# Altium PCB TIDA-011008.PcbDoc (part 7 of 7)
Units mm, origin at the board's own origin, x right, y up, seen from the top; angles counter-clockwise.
Board outline 252 x 205 mm, 4 copper layers (Top Layer, Inner Layer 1, Inner Layer 2, Bottom Layer), stack 1.926 mm thick; 517 components, 293 nets, 1426 pads, 1855 vias.
Unrouted connection lines stored in the file: 4.
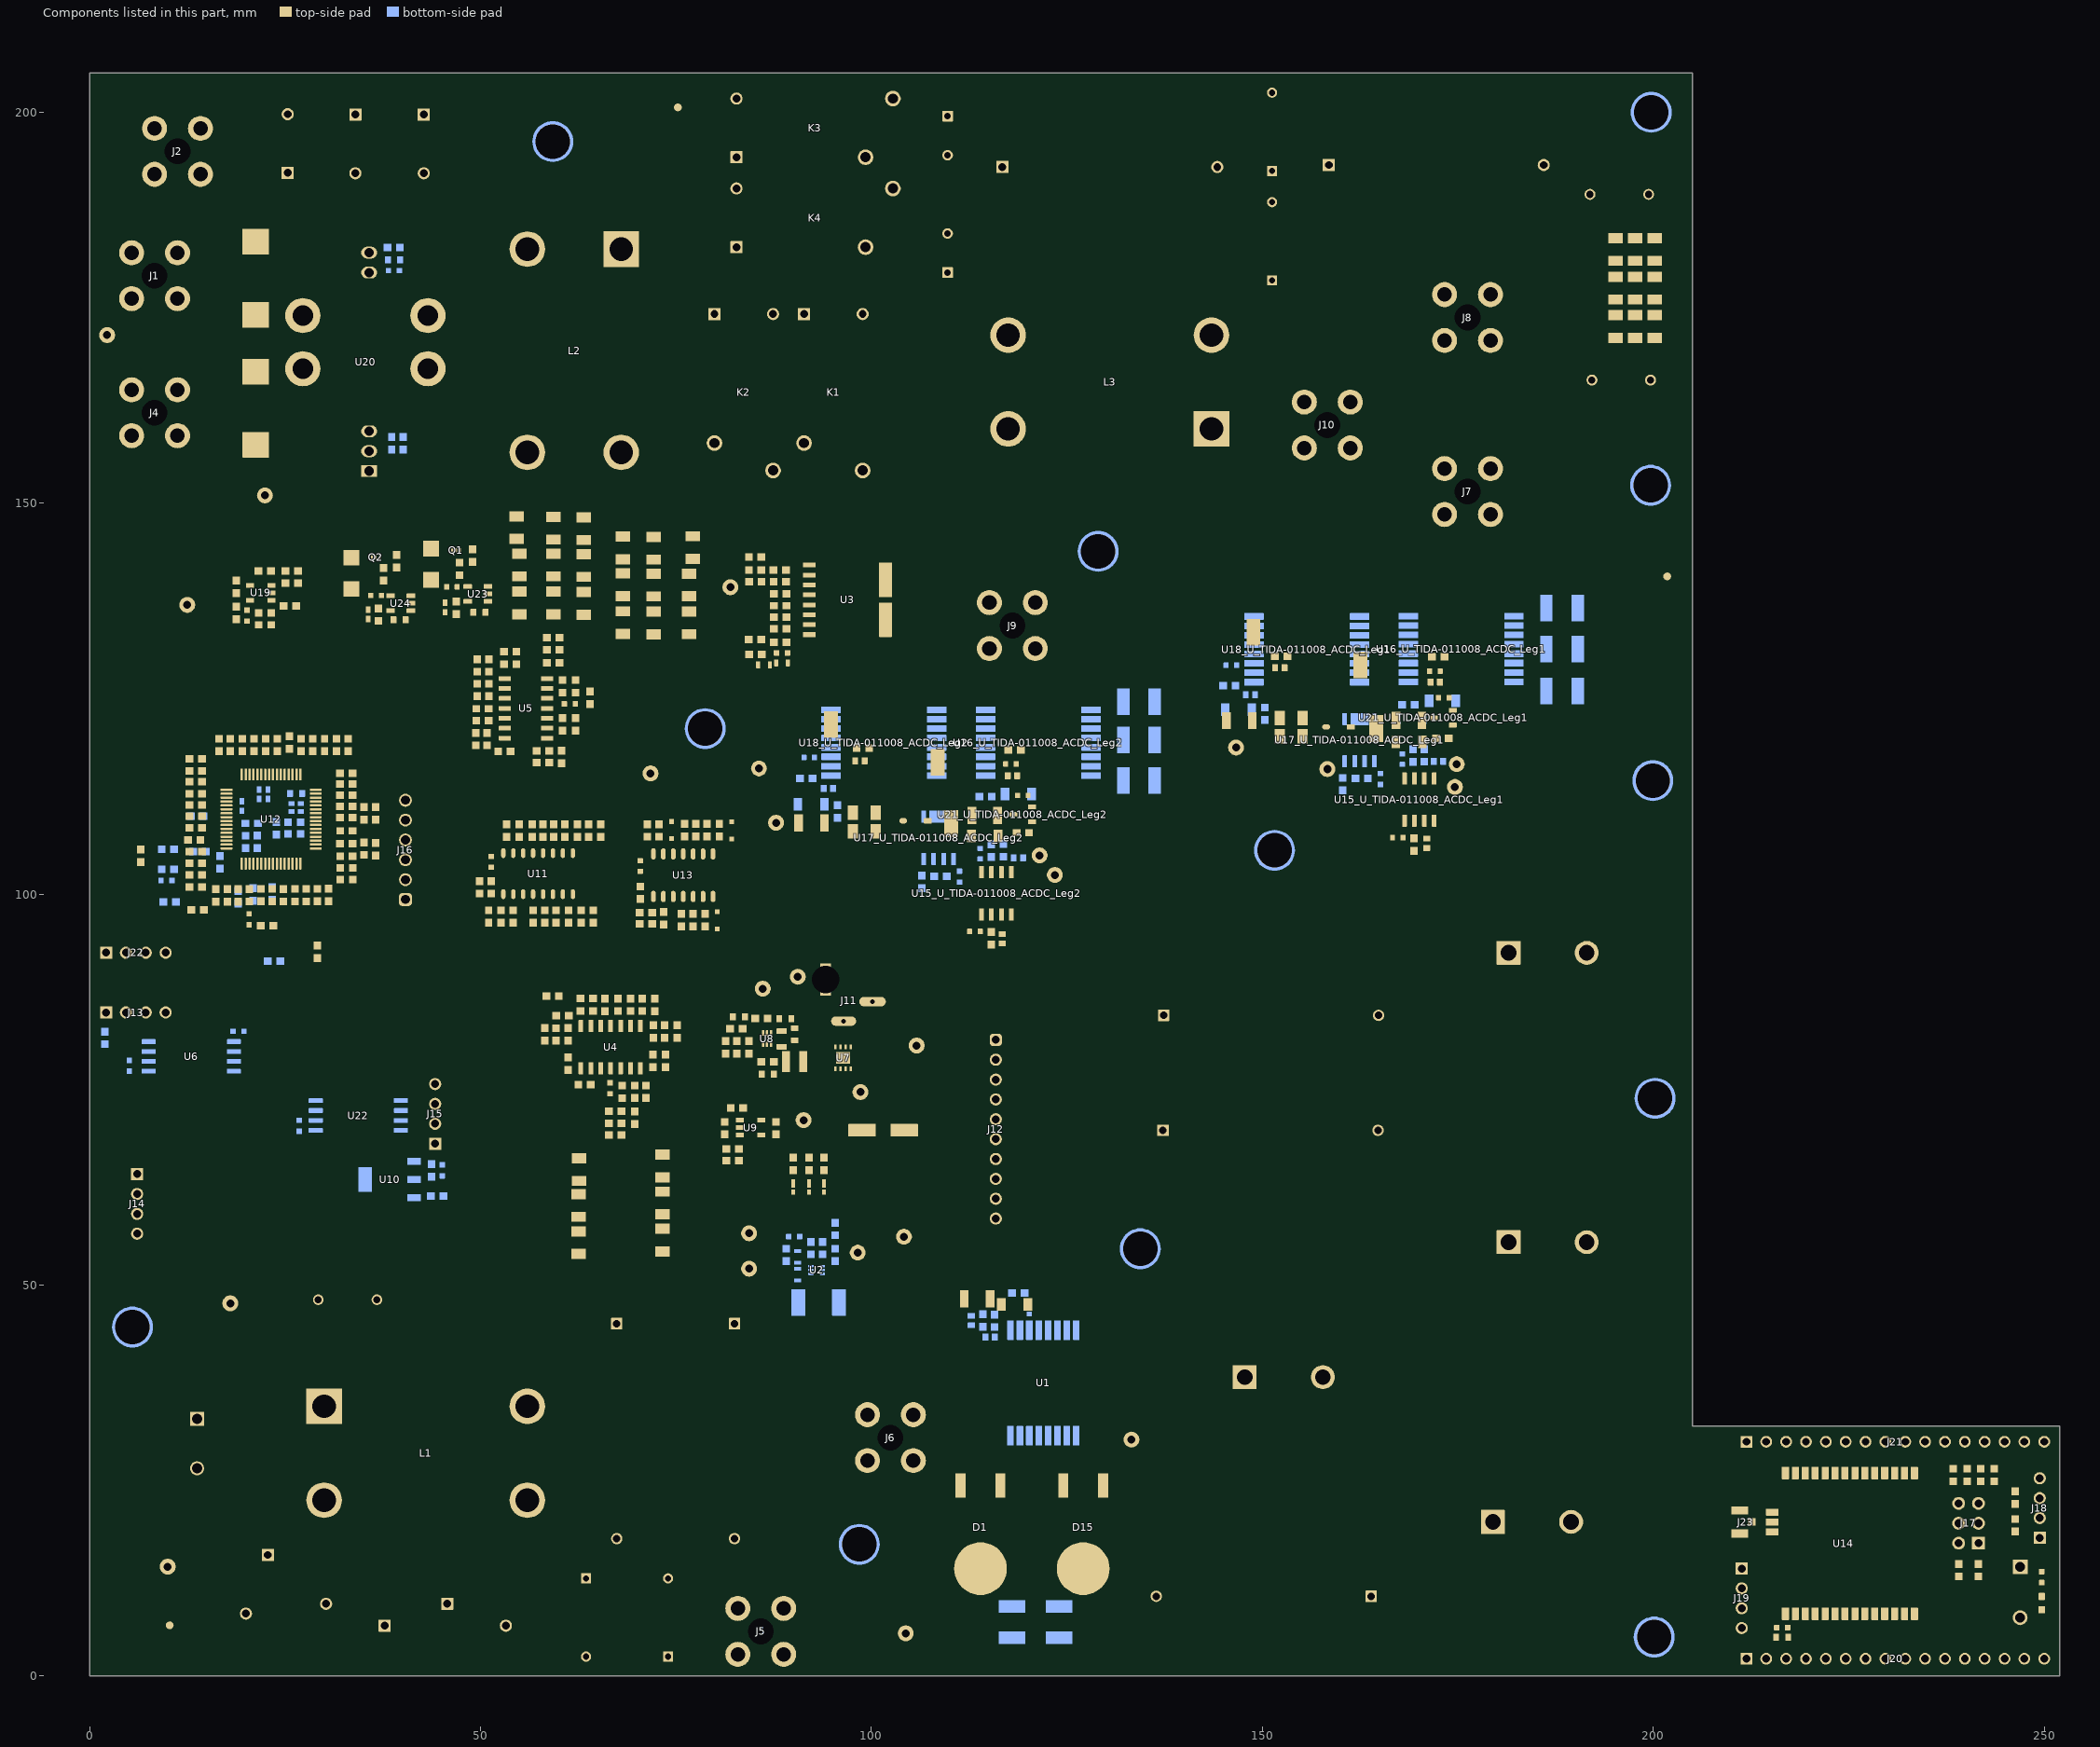
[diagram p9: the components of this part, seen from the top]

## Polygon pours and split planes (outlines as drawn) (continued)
DC_Bus- on Bottom Layer "BOTTOM_LAYER_DC_BUS-_P165" (solid, pour order 165): 143.567,131.562 139.741,127.736 136.518,127.736 135.5,128.754 135.5,139.871 140.784,145.155 143.567,142.372
VCC_3V3 on Bottom Layer "BOTTOM_LAYER_VCC_3V3_P149" (solid, pour order 149): 21.04,109.531 21.062,109.552 22.065,109.552 22.065,109.477 23.377,108.165 25.865,108.165 25.865,107.115 25.779,107.029 20.99,107.029 20.99,107.252
DC_Bus+ on Bottom Layer "BOTTOM_LAYER_DC_BUS+_P134" (solid, pour order 134): 125.15,129.32 130.36,134.53 132.475,134.53 133.061,133.944 133.061,104.966 132.596,104.501 129.823,104.501 125.15,109.174
DC_Bus- on Bottom Layer "BOTTOM_LAYER_DC_BUS-_P139" (solid, pour order 139): 189.51,140.915 190.871,142.277 197.293,142.277 203,136.569 203,118.589 200.908,116.496 190.215,116.496 189.51,117.202
DC_Bus- on Bottom Layer "BOTTOM_LAYER_DC_BUS-_P138" (solid, pour order 138): 135.519,128.873 136.074,129.429 138.071,129.429 139.75,127.75 139.75,108.665 137.235,106.15 136,106.15 135.5,106.65 135.5,128.864 135.519,128.882
DC_Bus- on Bottom Layer "BOTTOM_LAYER_DC_BUS-_P136" (solid, pour order 136): 153.242,131.562 153.904,132.224 153.904,144.337 153.086,145.155 140.784,145.155 135.76,140.131 135.76,133.842 138.04,131.562
DC_Bus- on Bottom Layer "BOTTOM_LAYER_DC_BUS-_P135" (solid, pour order 135): 102.67,119.566 103.271,120.168 103.271,127.176 102.697,127.75 93.153,127.75 91.378,125.974 91.378,120.742 92.553,119.567 92.553,119.566
AC_N on Bottom Layer "BOTTOM_LAYER_AC_N_P097" (solid, pour order 97): 4.715,167.2 15.05,167.2 23.75,158.5 23.75,154.94 22.31,153.5 5.42,153.5 2.719,156.201 2.719,165.203
NetF1_1 on Bottom Layer "BOTTOM_LAYER_NETF1_1_P089" (solid, pour order 89): 19.25,177 29,177 30,176 30,172.739 28.669,171.408 19.842,171.408 18.75,172.5 18.75,176.5
NetL2_3 on Bottom Layer "BOTTOM_LAYER_NETL2_3_P085" (solid, pour order 85): 43.687,179 50.75,179 62.5,167.25 62.5,154.339 60.411,152.25 52.75,152.25 50.5,154.5 50.5,165.75 44.511,171.739 41.908,171.739 41.125,172.522 41.125,176.438
VAC_N_SW on Bottom Layer "BOTTOM_LAYER_VAC_N_SW_P074" (solid, pour order 74): 118.25,204.25 153.25,204.25 154.25,203.25 154.25,200.5 153.25,199.5 125.375,199.5 124.25,198.375
VAC_N_SW on Bottom Layer "BOTTOM_LAYER_VAC_N_SW_P061" (solid, pour order 61): 19 vertices, not listed, extent 99.25,153.727 131.5,204.25
NetC26_1 on Bottom Layer "BOTTOM_LAYER_NETC26_1_P052" (solid, pour order 52): 140.75,163 149.565,163 152.565,166 165.987,166 168.25,163.737 168.25,158 164.5,154.25 141.25,154.25 140,155.5 140,162.25
NetC25_2 on Bottom Layer "BOTTOM_LAYER_NETC25_2_P050" (solid, pour order 50): 156.187,174.5 160.437,178.75 182.25,178.75 183.5,177.5 183.5,169.25 181.828,167.578 168.672,167.578 141.422,167.578 138.75,170.25 138.75,173.5 139.75,174.5
SN1 on Bottom Layer "BOTTOM_LAYER_SN1_P046" (solid, pour order 46): 160.298,121.504 164.589,121.504 165.104,122.018 165.104,130.139 166.527,131.562 170.124,131.562 173.212,134.65 173.212,139.962 181.039,147.789 181.039,155.224 179.979,156.284 171.363,156.284 157.75,142.671 157.75,124.052
PV_Input+ on Bottom Layer "BOTTOM_LAYER_PV_INPUT+_P019" (solid, pour order 19): 9,28.5 26,28.5 28.25,26.25 35.75,26.25 36.5,25.5 36.5,17 36.25,16.75 27.25,16.75 23.5,20.5 9.25,20.5 9,20.75
PV_Input+ on Bottom Layer "BOTTOM_LAYER_PV_INPUT+_P016" (solid, pour order 16): 11.5,20.75 15.25,17 15.25,8.5 18.25,5.5 30.8,5.5 32.241,6.941 32.241,10.121 31.162,11.2 21.3,11.2 18.25,14.25 18.25,20 19,20.75
PV_Input- on Bottom Layer "BOTTOM_LAYER_PV_INPUT-_P005" (solid, pour order 5): 9,30.25 26.25,30.25 28.5,28 35.5,28 36.5,29 36.5,38.5 35,40 9,40
DC_Bus- on Inner Layer 2 "INNER_LAYER_2_DC_BUS-_P255" (solid, remove dead copper, pour order 255): 77 vertices, not listed, extent 1,41.201 174.046,146.75
NetL2_3 on Inner Layer 2 "Inner Layer 2-NetL2_3" (solid, pour order 269): 40.959,173.023 42.574,171.408 47.694,171.408 49.5,173.214 49.5,184.679 40.774,193.405 23.75,193.405 23.75,189.588 25.838,187.5 39.638,187.5 43.687,183.45 43.687,179 40.959,176.271
DC_Bus- on Inner Layer 2 "Inner Layer 2-DC_Bus-" (solid, pour order 263): 67 vertices, not listed, extent 91.378,0.647 203,144.337
NetC8_2 on Inner Layer 2 "INNER_LAYER_2_NETC8_2_P240" (solid, pour order 240): 18 vertices, not listed, extent 53.125,0.25 91.553,25.261
NetL2_4 on Inner Layer 2 "INNER_LAYER_2_NETL2_4_P234" (solid, pour order 234): 40.56,167.885 42.175,169.5 47.083,169.5 48.25,168.333 48.25,165.5 46.25,163.5 42.496,163.5 40.56,165.435
GND_WiFi on Inner Layer 2 "INNER_LAYER_2_GND_WIFI_P229" (solid, pour order 229): 34.493,65.814 16.698,65.814 9.73,72.781 9.73,77.357 1.738,77.357 1,78.095 1,52.363 2.113,51.25 43.222,51.25 46.027,54.055 46.027,60.683
GND_WiFi on Inner Layer 2 "INNER_LAYER_2_GND_WIFI_P228" (solid, pour order 228): 45.447,60.164 46.076,60.793 46.076,76.108 45.194,76.99 39.545,76.99 38.18,75.625 38.18,66.667 37.327,65.814 34.493,65.814 34.137,65.458 34.137,62.256 36.228,60.164
GND_WiFi on Inner Layer 2 "INNER_LAYER_2_GND_WIFI_P225" (solid, pour order 225): 8.873,76.5 9.73,77.357 9.73,83.082 11,84.352 11,85.693 10.115,86.579 1.379,86.579 1,86.2 1,78.095 2.595,76.5 5.96,76.5
GND_WiFi on Inner Layer 2 "INNER_LAYER_2_GND_WIFI_P154" (solid, remove dead copper, pour order 154): 207.121,29.975 208.646,31.5 250.25,31.5 251.25,30.5 251.5,30.5 251.5,1.75 250.25,0.5 208.409,0.5 207.192,1.717 207.192,29.905
DC_Bus- on Inner Layer 2 "INNER_LAYER_2_DC_BUS-_P187" (solid, pour order 187): 23.413,146.42 28.872,151.879 28.872,161.383 33,165.51 33,181.626 36.124,184.75 40.06,184.75 41.06,183.75 41.043,183.733 41.043,179.247 39.623,177.827 39.623,162.105 42.294,159.433 42.294,149.839 45.594,146.54
SN_U_TIDA-011008_ACDC_Leg1 on Inner Layer 2 "INNER_LAYER_2_SN_U_TIDA-011008_ACDC_LEG1_P171" (solid, pour order 171): 166.487,129.119 166.487,130.092 168.748,132.354 172.643,132.354 176.166,128.831 176.166,113.901 175.922,113.657 168.072,113.657 166.487,115.243
SN_U_TIDA-011008_ACDC_Leg2 on Inner Layer 2 "INNER_LAYER_2_SN_U_TIDA-011008_ACDC_LEG2_P169" (solid, pour order 169): 112.302,119.292 119.737,119.292 122.75,116.28 122.75,103.866 120.69,101.807 113.82,101.807 111.798,103.829 111.798,118.788
AC_L on Inner Layer 2 "INNER_LAYER_2_AC_L_P099" (solid, pour order 99): 7.36,171.739 15,171.739 17,173.739 17,177.975 19.25,180.225 23.591,180.225 24.828,181.463 24.828,185.822 23.75,186.9 6.15,186.9 3.212,183.962 3.212,175.887
PV_Input- on Inner Layer 2 "INNER_LAYER_2_PV_INPUT-_P011" (solid, pour order 11): 25 vertices, not listed, extent 21.25,7 49,39.5
NetF2_1 on Inner Layer 2 "INNER_LAYER_2_NETF2_1_P091" (solid, pour order 91): 20.375,169.5 29.45,169.5 30.25,168.7 30.25,164.5 29.75,164 19.907,164 19,164.907 19,168.125
NetC26_1 on Inner Layer 2 "INNER_LAYER_2_NETC26_1_P209" (solid, pour order 209): 156,195.25 156.75,196 161,196 164,193 164,183.5 162.25,181.75 156.75,181.75 156,182.5
NetC26_1 on Inner Layer 2 "INNER_LAYER_2_NETC26_1_P207" (solid, pour order 207): 140.75,163 149.565,163 152.565,166 165.987,166 168.25,163.737 168.25,158 164.5,154.25 141.25,154.25 140,155.5 140,162.25
PE on Inner Layer 2 "INNER_LAYER_2_PE_P111" (solid, pour order 111): 7.541,189.709 16.459,189.709 25,198.25 26.957,198.25 30.708,202.001 38.423,202.001 41.831,198.593 43.593,198.593 44,199 44,202.193 41.943,204.25 7.897,204.25 5.5,201.853 5.5,191.75
NetC25_2 on Inner Layer 2 "INNER_LAYER_2_NETC25_2_P103" (solid, pour order 103): 188.125,194.875 189.75,193.25 192,193.25 193.99,191.26 193.99,187.99 193.25,187.25 188.125,187.25
AC_N on Inner Layer 2 "INNER_LAYER_2_AC_N_P096" (solid, pour order 96): 4.715,167.2 15.05,167.2 23.75,158.5 23.75,154.94 22.31,153.5 5.337,153.5 2.719,156.119 2.719,165.203
NetF1_1 on Inner Layer 2 "INNER_LAYER_2_NETF1_1_P086" (solid, pour order 86): 19.25,177 29,177 30,176 30,172.739 28.669,171.408 19.842,171.408 18.75,172.5 18.75,176.5
VAC_N_SW on Inner Layer 2 "INNER_LAYER_2_VAC_N_SW_P060" (solid, pour order 60): 19 vertices, not listed, extent 99.25,153.727 131.5,204.25
NetC25_2 on Inner Layer 2 "INNER_LAYER_2_NETC25_2_P054" (solid, pour order 54): 138.75,173.5 139.75,174.5 169,174.5 170.5,176 170.5,182.25 183.5,195.25 187.75,195.25 188.5,194.5 188.5,187.25 181.828,180.578 181.828,169.078 180.25,167.5 141.5,167.5 138.75,170.25
NetC12_1 on Inner Layer 2 "INNER_LAYER_2_NETC12_1_P029" (solid, pour order 29): 53.25,29 49.75,25.5 49.75,18.991 54.241,14.5 64.25,14.5 66,12.75 66,10.285 54.751,10.285 47.25,17.786 47.25,29 50.215,31.965 53.25,31.965
NetC12_1 on Inner Layer 2 "INNER_LAYER_2_NETC12_1_P022" (solid, pour order 22): 51.75,28.5 85.85,28.5 91.618,34.268 91.618,49.246 91.328,49.536 88.041,49.536 85.402,46.897 53.892,46.897 50.083,43.088 50.083,30.167
PV_Input+ on Inner Layer 2 "INNER_LAYER_2_PV_INPUT+_P018" (solid, pour order 18): 9,28.5 26,28.5 28.25,26.25 35.75,26.25 36.5,25.5 36.5,17 36.25,16.75 27.25,16.75 23.5,20.5 9.25,20.5 9,20.75
PV_Input+ on Inner Layer 2 "INNER_LAYER_2_PV_INPUT+_P015" (solid, pour order 15): 11.5,20.75 15.25,17 15.25,8.5 18.25,5.5 30.8,5.5 32.241,6.941 32.241,10.121 31.162,11.2 21.3,11.2 18.25,14.25 18.25,20 19,20.75
PV_Input- on Inner Layer 2 "INNER_LAYER_2_PV_INPUT-_P006" (solid, pour order 6): 9,30.25 26.25,30.25 28.5,28 35.5,28 36.5,29 36.5,38.5 35,40 9,40
DC_Bus- on Inner Layer 1 "INNER_LAYER_1_DC_BUS-_P157" (solid, remove dead copper, pour order 157): 77 vertices, not listed, extent 1,41.201 174.046,146.75
SN_U_TIDA-011008_ACDC_Leg1 on Inner Layer 1 "INNER_LAYER_1_SN_U_TIDA-011008_ACDC_LEG1_P174" (solid, pour order 174): 166.487,129.119 166.487,130.092 168.185,131.79 173.206,131.79 176.166,128.831 176.166,113.901 175.922,113.657 168.072,113.657 166.487,115.243
SN_U_TIDA-011008_ACDC_Leg2 on Inner Layer 1 "INNER_LAYER_1_SN_U_TIDA-011008_ACDC_LEG2_P173" (solid, pour order 173): 112.289,119.247 119.783,119.247 122.75,116.28 122.75,103.928 120.629,101.807 113.82,101.807 111.798,103.829 111.798,118.756
NetL2_4 on Inner Layer 1 "Inner Layer 1-NetL2_4" (solid, pour order 271): 22 vertices, not listed, extent 30.25,163.5 53,201.039
DC_Bus- on Inner Layer 1 "Inner Layer 1-DC_Bus-" (solid, pour order 264): 65 vertices, not listed, extent 91.378,0.647 203.021,144.337
DC_Bus- on Inner Layer 1 "INNER_LAYER_1_DC_BUS-_P242" (solid, pour order 242): 112.2,51.711 106.619,57.293 106.619,68.88 104.261,71.237 104.242,71.218 97.219,71.218 96.708,70.706 96.708,61.614 107.126,51.196 112.2,51.196
NetC8_2 on Inner Layer 1 "INNER_LAYER_1_NETC8_2_P239" (solid, pour order 239): 18 vertices, not listed, extent 52.994,0.25 91.421,25.261
NetC12_1 on Inner Layer 1 "INNER_LAYER_1_NETC12_1_P196" (solid, pour order 196): 80.808,46.897 85.402,46.897 88.041,49.536 91.33,49.536 91.33,49.534 91.658,49.206 91.658,36.908 90.735,35.985 84.639,35.985 78.75,41.874 78.75,44.839
NetC12_1 on Inner Layer 1 "INNER_LAYER_1_NETC12_1_P195" (solid, pour order 195): 50.083,31.411 50.083,43.088 53.892,46.897 71.553,46.897 74.25,44.2 74.25,30.75 72,28.5 52.994,28.5
GND_WiFi on Inner Layer 1 "INNER_LAYER_1_GND_WIFI_P153" (solid, remove dead copper, pour order 153): 207.121,29.975 208.646,31.5 250.25,31.5 251.25,30.5 251.5,30.5 251.5,1.75 250.25,0.5 208.409,0.5 207.192,1.717 207.192,29.905
AC_L on Inner Layer 1 "INNER_LAYER_1_AC_L_P100" (solid, pour order 100): 7.36,171.739 15,171.739 17,173.739 17,177.975 19.25,180.225 23.591,180.225 24.828,181.463 24.828,185.822 23.75,186.9 6.169,186.9 3.212,183.943 3.212,175.887
PV_Input- on Inner Layer 1 "INNER_LAYER_1_PV_INPUT-_P010" (solid, pour order 10): 25 vertices, not listed, extent 21.25,7 49,39.5
NetC24_1 on Inner Layer 1 "INNER_LAYER_1_NETC24_1_P059" (solid, pour order 59): 101,137.269 104.28,137.269 107.25,140.239 107.25,169.25 114.25,176.25 120.125,176.25 121.25,175.125 121.25,168 119.75,166.5 115.091,166.5 113.591,165 113.591,139.814 106.7,132.923 101,132.923
NetF2_1 on Inner Layer 1 "INNER_LAYER_1_NETF2_1_P092" (solid, pour order 92): 20.375,169.5 29.45,169.5 30.25,168.7 30.25,164.5 29.75,164 19.907,164 19,164.907 19,168.125
NetC25_2 on Inner Layer 1 "INNER_LAYER_1_NETC25_2_P199" (solid, pour order 199): 17 vertices, not listed, extent 169.5,167.15 193.99,195.25
VAC_N_SW on Inner Layer 1 "INNER_LAYER_1_VAC_N_SW_P197" (solid, pour order 197): 19 vertices, not listed, extent 99.25,153.727 131.5,204.25
DC_Bus- on Inner Layer 1 "INNER_LAYER_1_DC_BUS-_P183" (solid, pour order 183): 101.101,68.31 101.101,65.97 98.603,65.97 98.603,68.31
DC_Bus- on Inner Layer 1 "INNER_LAYER_1_DC_BUS-_P175" (solid, pour order 175): 18 vertices, not listed, extent 23.413,146.42 45.594,184.75
NetF1_1 on Inner Layer 1 "INNER_LAYER_1_NETF1_1_P088" (solid, pour order 88): 19.25,177 27.169,177 29.152,175.017 29.152,173.015 27.546,171.408 19.842,171.408 18.75,172.5 18.75,176.5
AC_N on Inner Layer 1 "INNER_LAYER_1_AC_N_P095" (solid, pour order 95): 4.7,167.2 15.05,167.2 23.75,158.5 23.75,154.94 22.31,153.5 5.391,153.5 2.719,156.172 2.719,165.219
VAC_N on Inner Layer 1 "INNER_LAYER_1_VAC_N_P071" (solid, pour order 71): 97.5,186.75 100.895,186.75 101.75,185.895 101.75,180.25 98.25,176.75 64.25,176.75 63.25,177.75 63.25,184.75 65.25,186.75 71.5,186.75 77.75,180.5 91.25,180.5
VAC_L_Relay on Inner Layer 1 "INNER_LAYER_1_VAC_L_RELAY_P065" (solid, pour order 65): 92.25,159.964 93.5,158.714 93.5,155.737 90.228,152.464 85.587,152.464 84.863,153.188 84.863,158.289 86.538,159.964
VAC_L on Inner Layer 1 "INNER_LAYER_1_VAC_L_P072" (solid, pour order 72): 53,186.25 59.25,186.25 61.75,183.75 61.75,177.691 65.691,173.75 75.5,173.75 83.478,165.771 83.478,155.315 82.164,154 78.5,154 70.5,162 68.433,162 50.5,179.933 50.5,183.75
VAC_L_SW on Inner Layer 1 "INNER_LAYER_1_VAC_L_SW_P069" (solid, pour order 69): 108.546,181.296 111.204,181.296 112.092,180.408 112.092,178.888 106.68,173.475 106.68,155.315 101.559,155.315 103.5,157.256 103.5,176.25
VAC_N_Relay on Inner Layer 1 "INNER_LAYER_1_VAC_N_RELAY_P067" (solid, pour order 67): 98.533,196.5 110.75,196.5 112.25,195 112.25,190.592 110.25,188.592 97.408,188.592 95.75,190.25 95.75,193.717
VAC_L_SW on Inner Layer 1 "INNER_LAYER_1_VAC_L_SW_P058" (solid, pour order 58): 17 vertices, not listed, extent 96.5,137.975 106.68,156.692
NetC26_1 on Inner Layer 1 "INNER_LAYER_1_NETC26_1_P053" (solid, pour order 53): 156.75,196 161,196 164,193 164,156 162,154 141.336,154 140,155.336 140,162.25 140.75,163 152,163 156,167 156,195.25
NetC12_1 on Inner Layer 1 "INNER_LAYER_1_NETC12_1_P028" (solid, pour order 28): 53.25,29 49.75,25.5 49.75,18.744 53.994,14.5 64.25,14.5 66,12.75 66,10.285 54.751,10.285 47.25,17.786 47.25,29 50.215,31.965 53.25,31.965
PV_Input+ on Inner Layer 1 "INNER_LAYER_1_PV_INPUT+_P017" (solid, pour order 17): 9,28.5 26,28.5 28.25,26.25 35.75,26.25 36.5,25.5 36.5,17 36.25,16.75 27.25,16.75 23.5,20.5 9.25,20.5 9,20.75
PV_Input+ on Inner Layer 1 "INNER_LAYER_1_PV_INPUT+_P014" (solid, pour order 14): 11.5,20.75 15.25,17 15.25,8.5 18.25,5.5 30.8,5.5 32.241,6.941 32.241,10.121 31.162,11.2 21.3,11.2 18.25,14.25 18.25,20 19,20.75
PV_Input- on Inner Layer 1 "INNER_LAYER_1_PV_INPUT-_P007" (solid, pour order 7): 9,30.25 26.25,30.25 28.5,28 35.5,28 36.5,29 36.5,38.5 35,40 9,40
no net on Bottom Solder "NONET_L-01_P-001" (solid): 124.068,19.02 133.318,19.02 134.587,17.751 134.587,11.444 134.541,11.444 133.847,10.75 123.835,10.75 123.258,11.327 123.258,18.21
no net on Bottom Solder "NONET_L-01_P-001" (solid): 108.731,18.78 117.981,18.78 119.25,17.511 119.25,11.204 119.204,11.204 118.509,10.509 108.498,10.509 107.921,11.087 107.921,17.97

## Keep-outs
Keep-Out Layer:
  text ".Layer_Name" at 2.656,-39.306 h0.6

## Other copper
Top Layer:
  pour cut-out: -1.658,44.466 ccw(c5.642,44.466) 5.642,37.166 ccw(c5.642,44.466) 12.942,44.466 ccw(c5.642,44.466) 5.642,51.766 ccw(c5.642,44.466)
  pour cut-out: 51.714,196.131 ccw(c59.014,196.131) 59.014,188.831 ccw(c59.014,196.131) 66.314,196.131 ccw(c59.014,196.131) 59.014,203.431 ccw(c59.014,196.131)
  pour cut-out: 192.472,114.457 ccw(c199.772,114.457) 199.772,107.157 ccw(c199.772,114.457) 207.072,114.457 ccw(c199.772,114.457) 199.772,121.757 ccw(c199.772,114.457)
  pour cut-out: 192.28,152.115 ccw(c199.58,152.115) 199.58,144.815 ccw(c199.58,152.115) 206.88,152.115 ccw(c199.58,152.115) 199.58,159.415 ccw(c199.58,152.115)
  pour cut-out: 192.214,199.881 ccw(c199.514,199.881) 199.514,192.581 ccw(c199.514,199.881) 206.814,199.881 ccw(c199.514,199.881) 199.514,207.181 ccw(c199.514,199.881)
  pour cut-out: 121.474,143.731 ccw(c128.774,143.731) 128.774,136.431 ccw(c128.774,143.731) 136.074,143.731 ccw(c128.774,143.731) 128.774,151.031 ccw(c128.774,143.731)
  pour cut-out: 71.214,121.057 ccw(c78.514,121.057) 78.514,113.757 ccw(c78.514,121.057) 85.814,121.057 ccw(c78.514,121.057) 78.514,128.357 ccw(c78.514,121.057)
  pour cut-out: 144.025,105.489 ccw(c151.325,105.489) 151.325,98.189 ccw(c151.325,105.489) 158.625,105.489 ccw(c151.325,105.489) 151.325,112.789 ccw(c151.325,105.489)
  pour cut-out: 192.707,73.779 ccw(c200.007,73.779) 200.007,66.479 ccw(c200.007,73.779) 207.307,73.779 ccw(c200.007,73.779) 200.007,81.079 ccw(c200.007,73.779)
  pour cut-out: 126.856,54.535 ccw(c134.156,54.535) 134.156,47.235 ccw(c134.156,54.535) 141.456,54.535 ccw(c134.156,54.535) 134.156,61.835 ccw(c134.156,54.535)
  pour cut-out: 90.866,17.078 ccw(c98.166,17.078) 98.166,9.778 ccw(c98.166,17.078) 105.466,17.078 ccw(c98.166,17.078) 98.166,24.378 ccw(c98.166,17.078)
  pour cut-out: 192.592,5.18 ccw(c199.892,5.18) 199.892,-2.12 ccw(c199.892,5.18) 207.192,5.18 ccw(c199.892,5.18) 199.892,12.48 ccw(c199.892,5.18)
  pour cut-out: 13.774,86.133 13.814,86.133 16.453,83.495 16.453,72.728 16.365,72.641 12.62,72.641 12.251,73.009 12.251,84.61
  pour cut-out: 30.796,67.157 30.796,76.822 34.917,80.943 47.427,80.943 48.665,79.704 48.665,79.129 42.737,79.129 42.737,67.097
  pour cut-out: 17.419,164.827 17.419,162.898 18.566,161.75 20.538,161.75
  text ".Layer_Name" at 2.656,-39.306 h0.6
Inner Layer 1:
  pour cut-out: 192.472,114.457 ccw(c199.772,114.457) 199.772,107.157 ccw(c199.772,114.457) 207.072,114.457 ccw(c199.772,114.457) 199.772,121.757 ccw(c199.772,114.457)
  pour cut-out: 192.28,152.115 ccw(c199.58,152.115) 199.58,144.815 ccw(c199.58,152.115) 206.88,152.115 ccw(c199.58,152.115) 199.58,159.415 ccw(c199.58,152.115)
  pour cut-out: 51.714,196.131 ccw(c59.014,196.131) 59.014,188.831 ccw(c59.014,196.131) 66.314,196.131 ccw(c59.014,196.131) 59.014,203.431 ccw(c59.014,196.131)
  pour cut-out: 192.214,199.881 ccw(c199.514,199.881) 199.514,192.581 ccw(c199.514,199.881) 206.814,199.881 ccw(c199.514,199.881) 199.514,207.181 ccw(c199.514,199.881)
  pour cut-out: 121.474,143.731 ccw(c128.774,143.731) 128.774,136.431 ccw(c128.774,143.731) 136.074,143.731 ccw(c128.774,143.731) 128.774,151.031 ccw(c128.774,143.731)
  pour cut-out: -1.658,44.466 ccw(c5.642,44.466) 5.642,37.166 ccw(c5.642,44.466) 12.942,44.466 ccw(c5.642,44.466) 5.642,51.766 ccw(c5.642,44.466)
  pour cut-out: 71.214,121.057 ccw(c78.514,121.057) 78.514,113.757 ccw(c78.514,121.057) 85.814,121.057 ccw(c78.514,121.057) 78.514,128.357 ccw(c78.514,121.057)
  pour cut-out: 144.025,105.489 ccw(c151.325,105.489) 151.325,98.189 ccw(c151.325,105.489) 158.625,105.489 ccw(c151.325,105.489) 151.325,112.789 ccw(c151.325,105.489)
  pour cut-out: 192.707,73.779 ccw(c200.007,73.779) 200.007,66.479 ccw(c200.007,73.779) 207.307,73.779 ccw(c200.007,73.779) 200.007,81.079 ccw(c200.007,73.779)
  pour cut-out: 126.856,54.535 ccw(c134.156,54.535) 134.156,47.235 ccw(c134.156,54.535) 141.456,54.535 ccw(c134.156,54.535) 134.156,61.835 ccw(c134.156,54.535)
  pour cut-out: 90.914,17.04 ccw(c98.214,17.04) 98.214,9.74 ccw(c98.214,17.04) 105.514,17.04 ccw(c98.214,17.04) 98.214,24.34 ccw(c98.214,17.04)
  pour cut-out: 192.592,5.18 ccw(c199.892,5.18) 199.892,-2.12 ccw(c199.892,5.18) 207.192,5.18 ccw(c199.892,5.18) 199.892,12.48 ccw(c199.892,5.18)
  pour cut-out: 114,79 114.01,78.99 117.929,78.99 117.929,75.29 117.942,75.276 113.95,75.276
  pour cut-out: 17.419,164.827 17.419,162.898 18.566,161.75 20.538,161.75
  pour cut-out: 29.508,68.446 21.137,68.446 22.452,67.132 28.194,67.132
  pour cut-out: 12.555,87.072 12.565,87.072 16.758,82.879 16.758,72.335 0.664,72.335 -0.001,73 0.015,73.016 0.015,87.059
  pour cut-out: 28.194,67.132 30.823,69.761 30.823,79.021 34.052,82.25 47.549,82.25 49.25,80.549 49.25,68.678 50.796,67.132
Inner Layer 2:
  pour cut-out: 192.472,114.457 ccw(c199.772,114.457) 199.772,107.157 ccw(c199.772,114.457) 207.072,114.457 ccw(c199.772,114.457) 199.772,121.757 ccw(c199.772,114.457)
  pour cut-out: 192.28,152.115 ccw(c199.58,152.115) 199.58,144.815 ccw(c199.58,152.115) 206.88,152.115 ccw(c199.58,152.115) 199.58,159.415 ccw(c199.58,152.115)
  pour cut-out: 51.714,196.131 ccw(c59.014,196.131) 59.014,188.831 ccw(c59.014,196.131) 66.314,196.131 ccw(c59.014,196.131) 59.014,203.431 ccw(c59.014,196.131)
  pour cut-out: 192.214,199.881 ccw(c199.514,199.881) 199.514,192.581 ccw(c199.514,199.881) 206.814,199.881 ccw(c199.514,199.881) 199.514,207.181 ccw(c199.514,199.881)
  pour cut-out: 121.474,143.731 ccw(c128.774,143.731) 128.774,136.431 ccw(c128.774,143.731) 136.074,143.731 ccw(c128.774,143.731) 128.774,151.031 ccw(c128.774,143.731)
  pour cut-out: -1.658,44.466 ccw(c5.642,44.466) 5.642,37.166 ccw(c5.642,44.466) 12.942,44.466 ccw(c5.642,44.466) 5.642,51.766 ccw(c5.642,44.466)
  pour cut-out: 71.214,121.057 ccw(c78.514,121.057) 78.514,113.757 ccw(c78.514,121.057) 85.814,121.057 ccw(c78.514,121.057) 78.514,128.357 ccw(c78.514,121.057)
  pour cut-out: 144.025,105.489 ccw(c151.325,105.489) 151.325,98.189 ccw(c151.325,105.489) 158.625,105.489 ccw(c151.325,105.489) 151.325,112.789 ccw(c151.325,105.489)
  pour cut-out: 192.707,73.779 ccw(c200.007,73.779) 200.007,66.479 ccw(c200.007,73.779) 207.307,73.779 ccw(c200.007,73.779) 200.007,81.079 ccw(c200.007,73.779)
  pour cut-out: 126.856,54.535 ccw(c134.156,54.535) 134.156,47.235 ccw(c134.156,54.535) 141.456,54.535 ccw(c134.156,54.535) 134.156,61.835 ccw(c134.156,54.535)
  pour cut-out: 90.914,17.04 ccw(c98.214,17.04) 98.214,9.74 ccw(c98.214,17.04) 105.514,17.04 ccw(c98.214,17.04) 98.214,24.34 ccw(c98.214,17.04)
  pour cut-out: 192.592,5.18 ccw(c199.892,5.18) 199.892,-2.12 ccw(c199.892,5.18) 207.192,5.18 ccw(c199.892,5.18) 199.892,12.48 ccw(c199.892,5.18)
  pour cut-out: 19.141,65.814 22.398,62.449 29.152,62.449 32.525,65.822
  pour cut-out: 77.491,59.067 99.645,59.04 100.089,58.595 100.089,58.512 78.503,58.512 77.491,57.5
  pour cut-out: 75.076,67.845 49.49,67.845 48.884,68.451 48.884,67.132 74.363,67.132
  pour cut-out: 75.153,66.342 97.099,66.342 98.603,67.845 75.076,67.845 74.363,67.132
  pour cut-out: 13.774,86.133 13.814,86.133 16.453,83.495 16.453,72.728 16.365,72.641 12.62,72.641 12.251,73.009 12.251,84.61
  pour cut-out: 31,68.5 30.796,68.704 30.796,76.822 34.917,80.943 47.427,80.943 48.665,79.704 48.665,79.129 38.397,79.129 35.91,76.642 35.91,68.475
  pour cut-out: 17.419,164.827 17.419,162.898 18.566,161.75 20.538,161.75
Bottom Layer:
  pour cut-out: 121.474,143.731 ccw(c128.774,143.731) 128.774,136.431 ccw(c128.774,143.731) 136.074,143.731 ccw(c128.774,143.731) 128.774,151.031 ccw(c128.774,143.731)
  pour cut-out: 192.472,114.457 ccw(c199.772,114.457) 199.772,107.157 ccw(c199.772,114.457) 207.072,114.457 ccw(c199.772,114.457) 199.772,121.757 ccw(c199.772,114.457)
  pour cut-out: 144.025,105.489 ccw(c151.325,105.489) 151.325,98.189 ccw(c151.325,105.489) 158.625,105.489 ccw(c151.325,105.489) 151.325,112.789 ccw(c151.325,105.489)
  pour cut-out: -1.658,44.466 ccw(c5.642,44.466) 5.642,37.166 ccw(c5.642,44.466) 12.942,44.466 ccw(c5.642,44.466) 5.642,51.766 ccw(c5.642,44.466)
  pour cut-out: 192.28,152.115 ccw(c199.58,152.115) 199.58,144.815 ccw(c199.58,152.115) 206.88,152.115 ccw(c199.58,152.115) 199.58,159.415 ccw(c199.58,152.115)
  pour cut-out: 51.714,196.131 ccw(c59.014,196.131) 59.014,188.831 ccw(c59.014,196.131) 66.314,196.131 ccw(c59.014,196.131) 59.014,203.431 ccw(c59.014,196.131)
  pour cut-out: 192.214,199.881 ccw(c199.514,199.881) 199.514,192.581 ccw(c199.514,199.881) 206.814,199.881 ccw(c199.514,199.881) 199.514,207.181 ccw(c199.514,199.881)
  pour cut-out: 71.214,121.057 ccw(c78.514,121.057) 78.514,113.757 ccw(c78.514,121.057) 85.814,121.057 ccw(c78.514,121.057) 78.514,128.357 ccw(c78.514,121.057)
  pour cut-out: 192.707,73.779 ccw(c200.007,73.779) 200.007,66.479 ccw(c200.007,73.779) 207.307,73.779 ccw(c200.007,73.779) 200.007,81.079 ccw(c200.007,73.779)
  pour cut-out: 126.856,54.535 ccw(c134.156,54.535) 134.156,47.235 ccw(c134.156,54.535) 141.456,54.535 ccw(c134.156,54.535) 134.156,61.835 ccw(c134.156,54.535)
  pour cut-out: 90.914,17.04 ccw(c98.214,17.04) 98.214,9.74 ccw(c98.214,17.04) 105.514,17.04 ccw(c98.214,17.04) 98.214,24.34 ccw(c98.214,17.04)
  pour cut-out: 192.592,5.18 ccw(c199.892,5.18) 199.892,-2.12 ccw(c199.892,5.18) 207.192,5.18 ccw(c199.892,5.18) 199.892,12.48 ccw(c199.892,5.18)
  pour cut-out: 92.733,51.763 94.144,51.763 94.334,51.573 94.331,51.57 94.331,51.288 92.802,51.288 92.693,51.397 92.693,51.692
  pour cut-out: 19.141,65.814 22.398,62.449 29.152,62.449 32.525,65.822
  pour cut-out: 13.774,86.133 13.814,86.133 16.453,83.495 16.453,72.728 16.365,72.641 12.62,72.641 12.251,73.009 12.251,84.61
  pour cut-out: 31,68.5 30.796,68.704 30.796,76.822 34.917,80.943 47.427,80.943 48.665,79.704 48.665,79.129 38.397,79.129 35.91,76.642 35.91,68.475
  pour cut-out: 17.419,164.827 17.419,162.898 18.566,161.75 20.538,161.75
  text ".Layer_Name" at 2.656,-39.306 h0.6

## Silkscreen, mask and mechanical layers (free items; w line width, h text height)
Top Overlay:
  text "'.PRJ_Number'.PCB_Rev" at 0.75,202.25 h3
  text "AC1" at 184.283,172.162 h1.52
  text "ACL" at 4.854,170.412 h1.52
  text "AC2" at 155.436,151.146 h1.52
  text "SN1" at 182.321,150.39 h1.52
  text "ACN" at 15.304,150.254 h1.52
  text "DC-" at 9.93,138.634 h1.52
  text "DC-" at 147.057,136.138 h1.52
  text "SN1" at 160.84,132.522 h1.52
  text "SN2" at 123.775,132.004 h1.52
  text "IAC_REF" at 81.213,127.554 h1.52 r90
  text "DC-" at 27.87,126.211 h1.52
  text "DC-" at 92.857,124.659 h1.52
  text "SN2" at 106.45,120.294 h1.52
  text "12V_ISO" at 160.904,116.109 h1.52
  text "SN" at 177.254,115.959 h1.52
  text "PWM_1B" at 143.784,115.671 h1.52
  text "DC-" at 154.867,113.163 h1.52
  text "PWM_2B" at 80.444,112.921 h1.52
  text "IAC_OUT" at 66.745,112.595 h1.52
  text "3V3" at 42.277,111.183 h1.52
  text "PWM_1A" at 173.091,110.411 h1.52
  text "TMS" at 42.277,108.494 h1.52
  text "SN" at 121.812,106.873 h1.52
  text "TCK" at 42.277,106.029 h1.52
  text "DC-" at 85.467,105.69 h1.52
  text "12V_ISO" at 105.893,104.515 h1.52
  text "GND" at 42.277,103.577 h1.52
  text "TDI" at 42.33,101.002 h1.52
  text "PWM2A" at 120.712,98.872 h1.52
  text "TDO" at 42.277,98.701 h1.52
  text "DC-" at 87.528,91.053 h1.52
  text "5V" at 82.587,89.05 h1.52
  text "Danger! High Voltage!" at 24.312,82.226 h1.52
  text "DC+" at 117.871,80.487 h1.52
  text "12V" at 108.006,80.434 h1.52
  text "Danger! High Temperature!" at 21.742,79.243 h1.52
  text "DC-" at 100.476,73.986 h1.52
  text "3V3" at 90.798,73.771 h1.52
  text "DC-" at 117.821,73.319 h1.52
  text "12V" at 117.821,70.571 h1.52
  text "DC-" at 117.746,67.949 h1.52
  text "5V_WiFi" at 117.956,60.724 h1.52
  text "iBOOST-" at 78.749,58.321 h1.52
  text "GND_WiFi" at 117.956,57.746 h1.52
  text "PWM_BOOST" at 101.989,53.165 h1.52
  text "iBOOST+" at 96.055,50.984 h1.52
  text "iBOOST_ref" at 75.892,49.008 h1.52
  text "PV-" at 20.504,47.147 h1.52
  text "DC-" at 123.008,37.374 h1.52
  text "SN_BST" at 120.594,33.466 h1.52
  text "BOOSTsw2" at 108.359,30.107 h1.52
  text "DC-" at 133.066,27.208 h1.52
  text "PV+" at 4.913,11.169 h1.52
  text "BOOSTsw1" at 91.504,7.254 h1.52
  text "DC+" at 99.898,2.749 h1.52
  text ".Layer_Name" at 2.656,-39.306 h0.6
Bottom Overlay:
  text ".Layer_Name" at 2.656,-39.306 h0.6
Top Paste:
  text ".Layer_Name" at 2.656,-39.306 h0.6
Bottom Paste:
  text ".Layer_Name" at 2.656,-39.306 h0.6
Top Solder:
  text ".Layer_Name" at 2.656,-39.306 h0.6
  text ".Layer_Name" at 2.656,-39.306 h0.6
Bottom Solder:
  text ".Layer_Name" at 2.656,-39.306 h0.6
Drill Guide:
  text ".Layer_Name" at 2.656,-39.306 h0.6
M1 Board Outline:
  the board outline again, w0.254
  text ".Layer_Name" at 2.656,-39.306 h0.6
M2 Board Dimensions:
  rectangle: -12,-24.485 -8.825,-21.31
  rectangle: -8.825,-27.66 0.7,-24.485
  lines w0.178: -12,-24.485 13.4,-24.485 ; -8.825,-27.66 -8.825,-21.31 ; -5.65,-27.66 -5.65,-21.31 ; 0.7,-27.66 0.7,-21.31 ; 7.05,-27.66 7.05,-21.31 ; -12,-27.66 13.4,-27.66 13.4,-21.31 -12,-21.31 -12,-27.66
  text ".Layer_Name" at 2.656,-39.306 h0.6
M3 3D STEP Top:
  text ".Layer_Name" at 2.656,-39.306 h0.6
M4 3D STEP Bottom:
  text ".Layer_Name" at 2.656,-39.306 h0.6
M5 Assembly Top:
  lines w0.254: -19.417,-41.126 148.223,-41.126 ; -19.417,-35.962 148.274,-35.962 ; -19.417,-30.797 -19.417,-46.291 82.31,-46.291 148.274,-46.291 148.274,-30.797 -19.404,-30.797 -19.404,-46.291 20.614,-46.291 ; 43.194,-46.291 43.194,-30.797 ; 75.376,-35.962 75.376,-30.797 ; 96.712,-35.962 96.712,-30.797 ; 112.511,-46.456 112.511,-41.304
  text "COMPONENTS MARKED 'DNP' SHOULD NOT BE POPULATED." at 17.299,-25.59 h0.6
  text "ASSEMBLY VARIANT:" at 17.286,-28.524 h0.6
  text ".VariantName" at 43.601,-28.524 h0.6
  text "PCB VIEWED FROM TOP SIDE" at -17.804,-34.154 h0.6
  text "BOARD #:" at 45.099,-34.154 h0.6
  text ".PRJ_Number" at 58.955,-34.154 h0.6
  text "REV:" at 80.405,-34.154 h0.6
  text ".PCB_Rev" at 87.809,-34.154 h0.6
  text "SVN REV:" at 101.69,-34.154 h0.6
  text ".VersionControl_RevNumber" at 114.543,-34.154 h0.6
  text "TID #:" at 45.099,-39.319 h0.6
  text ".TID" at 58.955,-39.319 h0.6
  text "PLOT NAME =" at -17.804,-44.534 h0.6
  text ".plot_File_Name" at 2.656,-44.534 h0.6
  text "GENERATED    :" at 45.15,-44.534 h0.6
  text ".Print_Date" at 67.235,-44.534 h0.6
  text ".Print_Time" at 85.752,-44.534 h0.6
  text "TEXAS INSTRUMENTS" at 117.87,-44.534 h0.6
M6 Assembly Bottom:
  lines w0.254: -19.43,-35.974 148.261,-35.974 ; -19.379,-41.139 148.261,-41.139 ; 16.334,-46.469 16.334,-41.317 ; 32.132,-35.974 32.132,-30.81 ; 53.468,-35.974 53.468,-30.81 ; 85.65,-46.304 85.65,-30.81 ; 108.231,-46.304 148.249,-46.304 148.249,-30.81 -19.43,-30.81 -19.43,-46.304 46.534,-46.304 148.261,-46.304 148.261,-30.81
  text "COMPONENTS MARKED 'DNP' SHOULD NOT BE POPULATED." at 142.991,-25.577 h0.6
  text ".VariantName" at 116.473,-28.524 h0.6
  text "ASSEMBLY VARIANT:" at 142.864,-28.524 h0.6
  text ".VersionControl_RevNumber" at 14.302,-34.167 h0.6
  text "SVN REV:" at 27.154,-34.167 h0.6
  text ".PCB_Rev" at 41.035,-34.167 h0.6
  text "REV:" at 48.439,-34.167 h0.6
  text ".PRJ_Number" at 69.89,-34.167 h0.6
  text "BOARD #:" at 83.745,-34.167 h0.6
  text "PCB VIEWED FROM BOTTOM SIDE" at 146.648,-34.167 h0.6
  text ".TID" at 69.89,-39.331 h0.6
  text "TID #:" at 83.745,-39.331 h0.6
  text "TEXAS INSTRUMENTS" at 10.974,-44.547 h0.6
  text ".Print_Time" at 43.093,-44.547 h0.6
  text ".Print_Date" at 61.609,-44.547 h0.6
  text "GENERATED    :" at 83.694,-44.547 h0.6
  text ".plot_File_Name" at 126.189,-44.547 h0.6
  text "PLOT NAME =" at 146.648,-44.547 h0.6
M9 Title Sheet:
  drawing of 50 lines, arcs and shapes, not listed
  text "A" at -22.579,157.595 h0.6
  text "A" at 353.341,157.595 h0.6
  text "B" at -22.579,97.143 h0.6
  text "B" at 353.341,97.143 h0.6
  text "C" at -22.579,36.818 h0.6
  text "C" at 353.341,36.818 h0.6
  text "PROJECT TITLE:" at 276.125,-10.452 h0.6
  text ".PRJ_Title" at 277.395,-13.838 h0.6
  text "DESIGNED FOR:" at 276.125,-18.097 h0.6
  text ".PRJ_Customer" at 277.395,-21.653 h0.6
  text "D" at -22.579,-23.38 h0.6
  text "D" at 353.341,-23.38 h0.6
  text "FILE NAME:" at 276.125,-25.717 h0.6
  text ".PCB_File_Name_No_Path" at 277.395,-28.765 h0.6
  text "Texas Instruments (TI) and/or its licensors do not warrant the accuracy or completeness of this specification" at 149.9,-32.876 h0.6
  text "ENGINEER:" at 276.125,-33.083 h0.6
  text "LAYOUT BY:" at 314.352,-33.083 h0.6
  text "or any information contained therein. TI and/or its licensors do not warrant that this design will meet" at 148.757,-35.737 h0.6
  text ".PRJ_Engineer" at 277.395,-37.02 h0.6
  text ".PCB_Layout" at 315.635,-37.02 h0.6
  text "the specifications, will be suitable for your application or fit for any particular purpose, or will operate in" at 148.757,-38.599 h0.6
  text ".Layer_Name" at 2.656,-39.306 h0.6
  text "ALTIUM DESIGNER VERSION:" at 314.352,-40.957 h0.6
  text "an implementation. TI and/or its licensors do not warrant that the design is production worthy. You should" at 148.757,-41.461 h0.6
  text "completely validate and test your design implementation to confirm the system functionality for your application." at 149.9,-44.322 h0.6
  text ".print_Scale" at 277.395,-44.343 h0.6
  text ".Application_BuildNumber" at 315.635,-44.343 h0.6
  text "1" at 6.792,-49.593 h0.6
  text "2" at 70.182,-49.593 h0.6
  text "3" at 133.411,-49.593 h0.6
  text "4" at 197.08,-49.593 h0.6
  text "5" at 260.555,-49.593 h0.6
  text "6" at 324.182,-49.593 h0.6
M10 Fab Notes:
  drawing of 189 lines, arcs and shapes, not listed
  text "DESIGN INFORMATION" at 302.503,143.947 h0.6
  text "MIN. TRACK WIDTH:" at 286.131,140.591 h0.6
  text "8" at 313.976,140.591 h0.6
  text "MIL" at 317.907,140.591 h0.6
  text "7.874" at 309.75,137.5 h0.6
  text "MIN. CLEARANCE:" at 286.131,137.438 h0.6
  text "MIL" at 317.907,137.438 h0.6
  text "MIN. VIA PAD SIZE:" at 286.131,134.285 h0.6
  text "24" at 313.214,134.285 h0.6
  text "MIL" at 317.907,134.285 h0.6
  text "0.05mm (2MIL)" at 303.784,130.986 h0.6
  text "MINIMUM ANNULAR RING" at 277.769,130.777 h0.6
  text "EXTERNAL" at 321.768,130.777 h0.6
  text "PER" at 282.849,127.98 h0.6
  text "IPC-D-275 CLASS 2 LEVEL C" at 288.437,127.98 h0.6
  text "MIL, HOLES" at 326.238,125.428 h0.6
  text "+/-" at 316.27,125.209 h0.6
  text "+/-" at 337.961,125.209 h0.6
  text "REGISTRATION TOLERANCES:" at 277.769,125.182 h0.6
  text "METAL" at 308.243,125.182 h0.6
  text "5" at 322.879,125.183 h0.6
  text "3" at 344.037,125.183 h0.6
  text "MIL" at 346.99,125.182 h0.6
  text "HOLE SIZE TOLERANCE (UNLESS OTHERWISE SPECIFIED):" at 277.769,122.685 h0.6
  text "+/-" at 337.961,122.612 h0.6
  text "3" at 344.037,122.585 h0.6
  text "MIL" at 346.99,122.585 h0.6
  text "MATERIAL:" at 275.87,119.089 h0.6
  text "FR-4 High Tg" at 300.926,115.824 h0.6
  text "X" at 297.257,115.622 h0.6
  text "FR-4" at 286.563,115.507 h0.6
  text "OTHER" at 324.358,115.507 h0.6
  text "62 MIL (1.6mm) +/-10%" at 294.694,111.874 h0.6
  text "X" at 291.643,111.812 h0.6
  text "THICKNESS:" at 277.769,111.665 h0.6
  text "OTHER" at 327.33,111.665 h0.6
  text "TOLERANCE:" at 277.769,108.152 h0.6
  text "X" at 299.314,108.152 h0.6
  text "ANSI IPC-6012 TYPE 3 CLASS 2" at 303.836,108.152 h0.6
  text "OTHER +/-" at 303.835,104.489 h0.6
  text "BOW & TWIST:" at 277.769,100.802 h0.6
  text "X" at 299.314,100.802 h0.6
  text "ANSI IPC-6012 TYPE 3 CLASS 2" at 303.836,100.802 h0.6
  text "OTHER +/-" at 303.835,97.076 h0.6
  text "DRILLING:" at 275.87,93.758 h0.6
  text "NC_DRILL FILES" at 320.599,91.086 h0.6
  text "REFERENCE:" at 277.769,90.986 h0.6
  text "X" at 294.463,90.984 h0.6
  text "AS SHOWN" at 298.984,90.986 h0.6
  text "X" at 317.348,90.986 h0.6
  text "OTHER" at 328.168,87.373 h0.6
  text "PTH COPPER THICKNESS:" at 277.761,87.283 h0.6
  text "X" at 306.697,87.283 h0.6
  text "20-30 um" at 309.948,87.283 h0.6
  text "BOARD FINISH:" at 275.87,83.534 h0.6
  text "SILKSCREEN:" at 279.812,80.737 h0.6
  text "X" at 304.14,80.737 h0.6
  text "TOP" at 307.112,80.737 h0.6
  text "X" at 317.094,80.737 h0.6
  text "BOTTOM" at 320.091,80.737 h0.6
  text "SILKSCREEN COLOR:" at 279.812,76.795 h0.6
  text "X" at 304.115,76.795 h0.6
  text "WHITE" at 307.112,76.795 h0.6
  text "OTHER" at 320.091,76.795 h0.6
  text "X" at 307.442,73.152 h0.6
  text "GREEN" at 310.439,73.152 h0.6
  text "OTHER" at 326.136,73.152 h0.6
  text "SOLDER RESIST COLOR:" at 279.812,72.977 h0.6
  text "X" at 307.442,69.234 h0.6
  text "MATTE" at 310.439,69.234 h0.6
  text "SEMI-GLOSS" at 326.125,69.217 h0.6
  text "IMMERSION GOLD (ENIG)" at 302.819,64.845 h0.6
  text "ENEPIG" at 336.793,64.662 h0.6
  text "SURFACE FINISH:" at 275.87,64.636 h0.6
  text "X" at 298.298,64.636 h0.6
  text "IMM. TIN/SILVER OR EQUIV" at 284.24,61.149 h0.6
  text "OTHER" at 320.599,61.049 h0.6
  text "ARRAY/PANEL:" at 275.87,57.102 h0.6
  text "CUT AND TRIM PER M1 BOARD OUTLINE" at 302.819,56.893 h0.6
  text "N.C. ROUTE" at 302.819,53.44 h0.6
  text "X" at 320.295,53.44 h0.6
  text "V. SCORE" at 324.816,53.44 h0.6
  text "CERTIFICATION:" at 275.87,50.16 h0.6
  text "MATERIALS AND WORKMANSHIP FOR ALL PCBS" at 294.285,50.16 h0.6
  text "TO MEET OR EXCEED THE REQUIREMENTS OF:" at 294.285,47.771 h0.6
  text "X" at 285.078,44.503 h0.6
  text "ANSI IPC-A-600F CLASS ->" at 288.329,44.503 h0.6
  text "X" at 330.188,44.503 h0.6
  text "2" at 332.982,44.503 h0.6
  text "1" at 324.981,44.465 h0.6
  text "3" at 341.973,44.465 h0.6
  text "X" at 305.702,40.752 h0.6
  text "RoHS" at 308.953,40.752 h0.6
  text "OTHER" at 325.321,40.752 h0.6
  text "PER ORDER" at 335.407,40.752 h0.6
  text "ALL BOARDS MUST MEET OR EXCEED UL94-V0 REQUIREMENTS." at 276.569,36.845 h0.6
  text "PCB MUST BEAR THE UL94V-0 UL REGISTERED MATERIAL ID NUMBER" at 276.569,33.897 h0.6
  text "ADDITIONAL REQUIREMENTS:" at 275.87,29.594 h0.6
  text "MICROSECTION:" at 277.769,26.873 h0.6
  text "YES" at 300.775,26.873 h0.6
  text "REQUIRED" at 322.657,23.207 h0.6
  text "BARE BOARD ELEC. TEST:" at 277.769,23.134 h0.6
  text "NONE" at 310.935,23.134 h0.6
  text "X" at 319.66,23.134 h0.6
  text "PER ORDER" at 337.693,23.134 h0.6
  text "XX MIL VIAS REQUIRE NON-CONDUCTIVE FILL AND PLANARIZE" at 282.04,17.928 h0.6
  text "XX MIL VIAS REQUIRE CONDUCTIVE FILL AND PLANARIZE" at 282.243,15.287 h0.6
  text "OUTER XX MIL TRACES REQUIRE 50 OHM SINGLE-ENDED IMPEDANCE" at 282.218,11.137 h0.6
  text "LAYER 2 & 3 (INNER LAYERS) XX MIL WIDE, XX MIL SPACE / TRACES REQUIRE 100 OHM DIFFERENTIAL IMPEDANCE" at 282.015,5.15 h0.6
  text ".Layer_Name" at 2.656,-39.306 h0.6
M11 Gerber Information:
  lines w0.254: -19.417,-41.126 148.223,-41.126 ; -19.417,-35.962 148.274,-35.962 ; -19.417,-30.797 -19.417,-46.291 82.31,-46.291 148.274,-46.291 148.274,-30.797 -19.404,-30.797 -19.404,-46.291 20.614,-46.291 ; 43.194,-46.291 43.194,-30.797 ; 75.376,-35.962 75.376,-30.797 ; 96.712,-35.962 96.712,-30.797 ; 112.511,-46.456 112.511,-41.304
  text "ALL ARTWORK VIEWED FROM TOP SIDE" at -17.804,-34.154 h0.6
  text "BOARD #:" at 45.099,-34.154 h0.6
  text ".PRJ_Number" at 58.955,-34.154 h0.6
  text "REV:" at 80.405,-34.154 h0.6
  text ".PCB_Rev" at 87.809,-34.154 h0.6
  text "SVN REV:" at 101.69,-34.154 h0.6
  text ".VersionControl_RevNumber" at 114.543,-34.154 h0.6
  text "LAYER NAME =" at -17.804,-39.306 h0.6
  text "TID #:" at 45.099,-39.319 h0.6
  text ".TID" at 58.955,-39.319 h0.6
  text "PLOT NAME =" at -17.804,-44.534 h0.6
  text ".plot_File_Name" at 2.656,-44.534 h0.6
  text "GENERATED    :" at 45.15,-44.534 h0.6
  text ".Print_Date" at 67.235,-44.534 h0.6
  text ".Print_Time" at 85.752,-44.534 h0.6
  text "TEXAS INSTRUMENTS" at 117.87,-44.534 h0.6
M12 Stackup:
  drawing of 306 lines, arcs and shapes, not listed
  text "Layer" at 234.592,256.854 h0.6
  text "Name" at 239,256.854 h0.6
  text "Material" at 248.605,256.854 h0.6
  text "Thickness" at 257.511,256.854 h0.6
  text "Constant" at 264.317,256.854 h0.6
  text "Board Layer Stack" at 270.324,256.854 h0.6
  text "Top Overlay" at 239,255.654 h0.6
  text "Top Solder" at 239,254.454 h0.6
  text "Solder Resist" at 248.605,254.454 h0.6
  text "0.40mil" at 257.511,254.454 h0.6
  text "3.5" at 264.317,254.454 h0.6
  text "1" at 234.592,253.254 h0.6
  text "Top Layer" at 239,253.254 h0.6
  text "2.76mil" at 257.511,253.254 h0.6
  text "Dielectric 1" at 239,252.054 h0.6
  text "PP-006" at 248.605,252.054 h0.6
  text "2.80mil" at 257.511,252.054 h0.6
  text "4.1" at 264.317,252.054 h0.6
  text "2" at 234.592,250.854 h0.6
  text "Inner Layer 1" at 239,250.854 h0.6
  text "CF-004" at 248.605,250.854 h0.6
  text "2.76mil" at 257.511,250.854 h0.6
  text "Dielectric1" at 239,249.654 h0.6
  text "FR-4 High Tg" at 248.605,249.654 h0.6
  text "59.20mil" at 257.511,249.654 h0.6
  text "4.8" at 264.317,249.654 h0.6
  text "3" at 234.592,248.454 h0.6
  text "Inner Layer 2" at 239,248.454 h0.6
  text "CF-004" at 248.605,248.454 h0.6
  text "2.76mil" at 257.511,248.454 h0.6
  text "Dielectric 2" at 239,247.254 h0.6
  text "PP-006" at 248.605,247.254 h0.6
  text "2.80mil" at 257.511,247.254 h0.6
  text "4.1" at 264.317,247.254 h0.6
  text "4" at 234.592,246.054 h0.6
  text "Bottom Layer" at 239,246.054 h0.6
  text "2.76mil" at 257.511,246.054 h0.6
  text "Bottom Solder" at 239,244.854 h0.6
  text "Solder Resist" at 248.605,244.854 h0.6
  text "0.40mil" at 257.511,244.854 h0.6
  text "3.5" at 264.317,244.854 h0.6
  text "Bottom Overlay" at 239,243.654 h0.6
  text ".Layer_Name" at 2.656,-39.306 h0.6
M13 Component Bodies Top:
  text ".Layer_Name" at 2.656,-39.306 h0.6
M14 Component Bodies Bottom:
  text ".Layer_Name" at 2.656,-39.306 h0.6
M15 Courtyards Top:
  text ".Layer_Name" at 2.656,-39.306 h0.6
M16 Courtyards Bottom:
  text ".Layer_Name" at 2.656,-39.306 h0.6
Drill Drawing:
  drawing of 181 lines, arcs and shapes, not listed
  text "Symbol" at 267.756,217.162 h0.72
  text "Quantity" at 270.757,217.162 h0.72
  text "Finished Hole Size" at 274.073,217.162 h0.72
  text "Plated" at 280.43,217.162 h0.72
  text "Hole Type" at 283.017,217.162 h0.72
  text "Drill Layer Pair" at 286.763,217.162 h0.72
  text "Hole Tolerance" at 293.977,217.162 h0.72
  text "9" at 270.757,215.923 h0.6
  text "129.92mil (3.300mm)" at 274.073,215.923 h0.6
  text "NPTH" at 280.43,215.923 h0.6
  text "Round" at 283.017,215.923 h0.6
  text "Top Layer - Bottom Layer" at 286.763,215.923 h0.6
  text "12" at 270.757,214.683 h0.6
  text "173.23mil (4.400mm)" at 274.073,214.683 h0.6
  text "NPTH" at 280.43,214.683 h0.6
  text "Round" at 283.017,214.683 h0.6
  text "Top Layer - Bottom Layer" at 286.763,214.683 h0.6
  text "H" at 267.398,214.429 h0.55
  text "1853" at 270.757,213.443 h0.6
  text "10.00mil (0.254mm)" at 274.073,213.443 h0.6
  text "PTH" at 280.43,213.443 h0.6
  text "Round" at 283.017,213.443 h0.6
  text "Top Layer - Bottom Layer" at 286.763,213.443 h0.6
  text "G" at 267.398,213.19 h0.55
  text "8" at 270.757,212.204 h0.6
  text "31.50mil (0.800mm)" at 274.073,212.204 h0.6
  text "PTH" at 280.43,212.204 h0.6
  text "Round" at 283.017,212.204 h0.6
  text "Top Layer - Bottom Layer" at 286.763,212.204 h0.6
  text "4" at 270.757,210.964 h0.6
  text "33.47mil (0.850mm)" at 274.073,210.964 h0.6
  text "PTH" at 280.43,210.964 h0.6
  text "Round" at 283.017,210.964 h0.6
  text "Top Layer - Bottom Layer" at 286.763,210.964 h0.6
  text "6" at 270.757,209.725 h0.6
  text "35.43mil (0.900mm)" at 274.073,209.725 h0.6
  text "PTH" at 280.43,209.725 h0.6
  text "Round" at 283.017,209.725 h0.6
  text "Top Layer - Bottom Layer" at 286.763,209.725 h0.6
  text "B" at 267.398,209.471 h0.55
  text "10" at 270.757,208.485 h0.6
  text "37.40mil (0.950mm)" at 274.073,208.485 h0.6
  text "PTH" at 280.43,208.485 h0.6
  text "Round" at 283.017,208.485 h0.6
  text "Top Layer - Bottom Layer" at 286.763,208.485 h0.6
  text "A" at 267.398,208.231 h0.55
  text "58" at 270.757,207.245 h0.6
  text "39.37mil (1.000mm)" at 274.073,207.245 h0.6
  text "PTH" at 280.43,207.245 h0.6
  text "Round" at 283.017,207.245 h0.6
  text "Top Layer - Bottom Layer" at 286.763,207.245 h0.6
  text "56" at 270.757,206.006 h0.6
  text "40.00mil (1.016mm)" at 274.073,206.006 h0.6
  text "PTH" at 280.43,206.006 h0.6
  text "Round" at 283.017,206.006 h0.6
  text "Top Layer - Bottom Layer" at 286.763,206.006 h0.6
  text "10" at 270.757,204.766 h0.6
  text "40.16mil (1.020mm)" at 274.073,204.766 h0.6
  text "PTH" at 280.43,204.766 h0.6
  text "Round" at 283.017,204.766 h0.6
  text "Top Layer - Bottom Layer" at 286.763,204.766 h0.6
  text "E" at 267.398,204.512 h0.55
  text "6" at 270.757,203.526 h0.6
  text "45.28mil (1.150mm)" at 274.073,203.526 h0.6
  text "PTH" at 280.43,203.526 h0.6
  text "Round" at 283.017,203.526 h0.6
  text "Top Layer - Bottom Layer" at 286.763,203.526 h0.6
  text "5" at 270.757,202.287 h0.6
  text "47.24mil (1.200mm)" at 274.073,202.287 h0.6
  text "PTH" at 280.43,202.287 h0.6
  text "Round" at 283.017,202.287 h0.6
  text "Top Layer - Bottom Layer" at 286.763,202.287 h0.6
  text "F" at 267.398,202.033 h0.55
  text "2" at 270.757,201.047 h0.6
  text "48.82mil (1.240mm)" at 274.073,201.047 h0.6
  text "PTH" at 280.43,201.047 h0.6
  text "Round" at 283.017,201.047 h0.6
  text "Top Layer - Bottom Layer" at 286.763,201.047 h0.6
  text "10" at 270.757,199.808 h0.6
  text "51.18mil (1.300mm)" at 274.073,199.808 h0.6
  text "PTH" at 280.43,199.808 h0.6
  text "Round" at 283.017,199.808 h0.6
  text "Top Layer - Bottom Layer" at 286.763,199.808 h0.6
  text "C" at 267.398,199.554 h0.55
  text "36" at 270.757,198.568 h0.6
  text "72.84mil (1.850mm)" at 274.073,198.568 h0.6
  text "PTH" at 280.43,198.568 h0.6
  text "Round" at 283.017,198.568 h0.6
  text "Top Layer - Bottom Layer" at 286.763,198.568 h0.6
  text "8" at 270.757,197.328 h0.6
  text "78.74mil (2.000mm)" at 274.073,197.328 h0.6
  text "PTH" at 280.43,197.328 h0.6
  text "Round" at 283.017,197.328 h0.6
  text "Top Layer - Bottom Layer" at 286.763,197.328 h0.6
  text "D" at 267.398,197.074 h0.55
  text "4" at 270.757,196.089 h0.6
  text "102.36mil (2.600mm)" at 274.073,196.089 h0.6
  text "PTH" at 280.43,196.089 h0.6
  text "Round" at 283.017,196.089 h0.6
  text "Top Layer - Bottom Layer" at 286.763,196.089 h0.6
  text "12" at 270.757,194.849 h0.6
  text "118.11mil (3.000mm)" at 274.073,194.849 h0.6
  text "PTH" at 280.43,194.849 h0.6
  text "Round" at 283.017,194.849 h0.6
  text "Top Layer - Bottom Layer" at 286.763,194.849 h0.6
  text "1" at 270.757,193.609 h0.6
  text "23.62mil (0.600mm)" at 274.073,193.609 h0.6
  text "PTH" at 280.43,193.609 h0.6
  text "Slot" at 283.017,193.609 h0.6
  text "Top Layer - Bottom Layer" at 286.763,193.609 h0.6
  text "1" at 270.757,192.37 h0.6
  text "23.62mil (0.600mm)" at 274.073,192.37 h0.6
  text "PTH" at 280.43,192.37 h0.6
  text "Slot" at 283.017,192.37 h0.6
  text "Top Layer - Bottom Layer" at 286.763,192.37 h0.6
  text "1" at 270.757,191.13 h0.6
  text "137.79mil (3.500mm)" at 274.073,191.13 h0.6
  text "PTH" at 280.43,191.13 h0.6
  text "Slot" at 283.017,191.13 h0.6
  text "Top Layer - Bottom Layer" at 286.763,191.13 h0.6
  text "2112 Total" at 270.757,189.891 h0.6
  text "Slot definitions :" at 267.756,189.023 h0.6
  text "Routed Path Length" at 272.243,189.023 h0.6
  text "= Calculated from tool start centre position to tool end centre position." at 277.618,189.023 h0.6
  text "Hole Length" at 272.243,188.527 h0.6
  text "= Routed Path Length + Tool Size = Slot length as defined in the PCB layout" at 275.628,188.527 h0.6
  text ".Layer_Name" at 2.656,-39.306 h0.6
M17 Embedded Cavity:
  text ".Layer_Name" at 2.656,-39.306 h0.6
M18 Embedded Assembly:
  text ".Layer_Name" at 2.656,-39.306 h0.6
M19 Embedded Keepout:
  text ".Layer_Name" at 2.656,-39.306 h0.6

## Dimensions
-12,-27.66 to 13.4,-27.66 on M2 Board Dimensions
